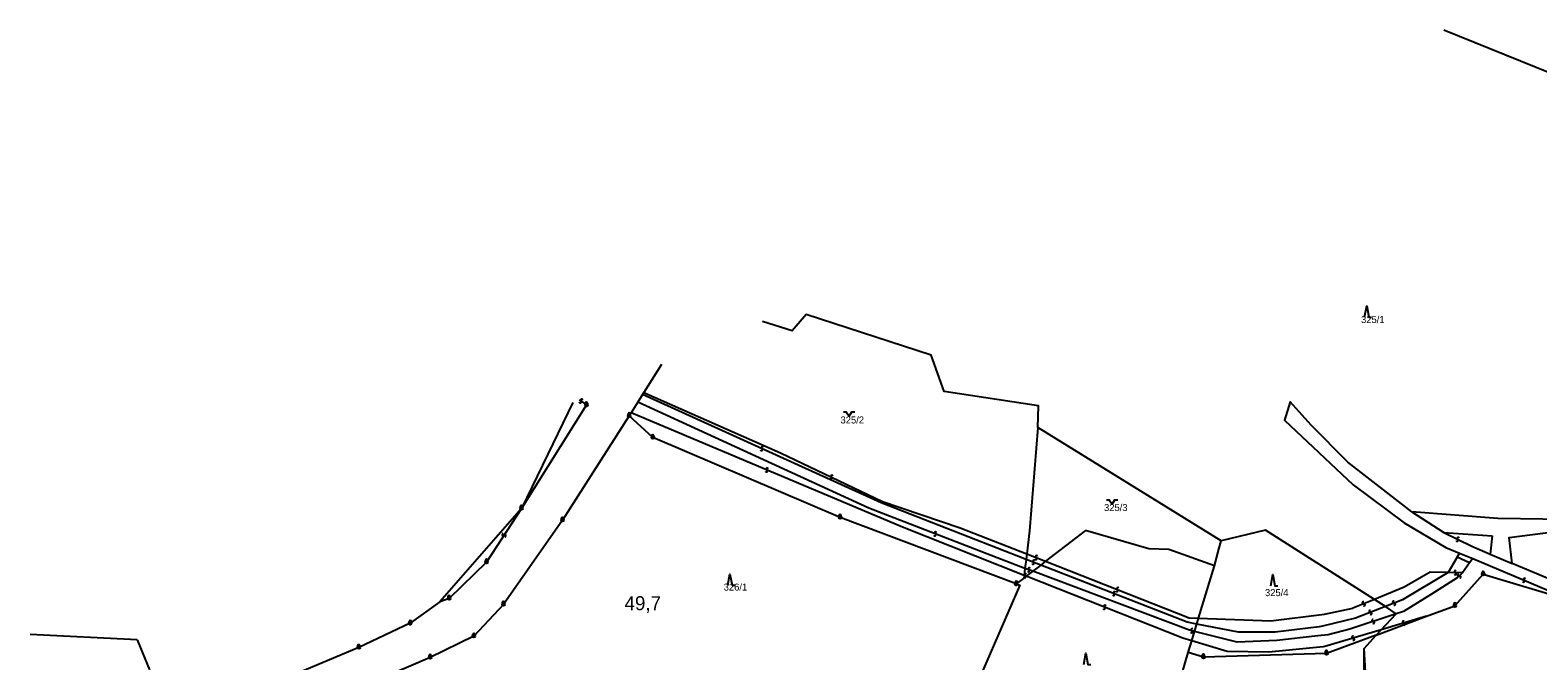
# Model space of a CAD drawing. Extents: x -680102 to -677253, y -1007548 to -1006096.
# Drawn here: x -678248 to -677710, y -1006321 to -1006096 of the extents above; entities that cross this region are included whole.
import ezdxf

# ---------------------------------------------------------------- set-up
doc = ezdxf.new("R2010")
doc.units = 0
for name, color, linetype, lineweight in [('1', 7, 'Continuous', 25), ('11', 7, 'Continuous', 25), ('13', 7, 'Continuous', 25), ('24', 7, 'Continuous', 25), ('25', 7, 'Continuous', 25), ('4', 7, 'Continuous', 25)]:
    doc.layers.add(name, color=color, linetype=linetype, lineweight=lineweight)
doc.layers.add('18', color=7, linetype='Continuous')
doc.layers.add('56', color=7, linetype='Continuous')

msp = doc.modelspace()

# ---------------------------------------------------------------- linework, layer by layer
at = {"layer": '1'}
for p, q in [((-678029.28, -1006226.2), (-678031.01, -1006228.95)), ((-677888.41, -1006237.95), (-677891.42, -1006274.73)), ((-678072.49, -1006266.77), (-678101.56, -1006300)), ((-677893, -1006288.11), (-677893.3, -1006290.62)), ((-677892.62, -1006284.91), (-677893, -1006288.11)), ((-677887.38, -1006286.95), (-677890.24, -1006289.15)), ((-677893.42, -1006291.6), (-677896.13, -1006293.68)), ((-677893.3, -1006290.62), (-677893.42, -1006291.6)), ((-677739.77, -1006301.43), (-677729.71, -1006290.21)), ((-677729.71, -1006290.21), (-677696.92, -1006300.06)), ((-678101.56, -1006300), (-678112.1, -1006307.67)), ((-678112.1, -1006307.67), (-678130.46, -1006316.3)), ((-678209.48, -1006313.6), (-678247.59, -1006311.68)), ((-678209.48, -1006313.6), (-678205.1, -1006324.25)), ((-677772.05, -1006316.61), (-677767.82, -1006311.9)), ((-678130.46, -1006316.3), (-678180.18, -1006337.1)), ((-677770.39, -1006346.95), (-677772.05, -1006316.61))]:
    msp.add_line(p, q, dxfattribs=at)
for points in [[(-677768.42, -1006299.16), (-677807.32, -1006274.53), (-677823.04, -1006278.3), (-677888.41, -1006237.95), (-677888.18, -1006230.26), (-677921.81, -1006225.09), (-677926.47, -1006212.23), (-677971.04, -1006197.75), (-677976.03, -1006203.56), (-677986.61, -1006200.22)], [(-678022.58, -1006215.58), (-678028.83, -1006225.49), (-678029.28, -1006226.2)], [(-678054.11, -1006229.04), (-678063.06, -1006247.41), (-678072.49, -1006266.77)], [(-678031.01, -1006228.95), (-678033.38, -1006232.71), (-678034.06, -1006233.78)], [(-677896.13, -1006293.68), (-677958.9, -1006269.98), (-678025.7, -1006241.54), (-678034.06, -1006233.78), (-678057.89, -1006270.97), (-678078.93, -1006300.97), (-678089.46, -1006312.29), (-678105.02, -1006319.82), (-678141.98, -1006335.73), (-678158.36, -1006345.46), (-678162.46, -1006351.78)], [(-677891.42, -1006274.73), (-677892.39, -1006282.96), (-677892.62, -1006284.91)], [(-677871.38, -1006274.64), (-677885.64, -1006285.61), (-677887.38, -1006286.95)], [(-677825.43, -1006287.18), (-677841.78, -1006281.38), (-677848.81, -1006281.2), (-677871.38, -1006274.64)], [(-677825.43, -1006287.18), (-677823.86, -1006281.33), (-677823.04, -1006278.3)], [(-677834.8, -1006318.04), (-677833.56, -1006313.95), (-677832.54, -1006310.59), (-677831.75, -1006307.98), (-677831.1, -1006305.85), (-677825.43, -1006287.18)], [(-677896.13, -1006293.68), (-677894.83, -1006294.13), (-677918.4, -1006348.18)], [(-677890.24, -1006289.15), (-677892.54, -1006290.92), (-677893.42, -1006291.6)], [(-677767.82, -1006311.9), (-677766.05, -1006310.02), (-677760.67, -1006304.32), (-677764.56, -1006301.73), (-677768.42, -1006299.16)], [(-677767.82, -1006311.9), (-677749.87, -1006305.2), (-677739.77, -1006301.43)], [(-677767.82, -1006311.9), (-677785.59, -1006318.42), (-677829.42, -1006319.73), (-677834.8, -1006318.04)], [(-677845.59, -1006355.04), (-677844.44, -1006351.14), (-677834.8, -1006318.04)]]:
    msp.add_lwpolyline(points, dxfattribs=at)
at = {"layer": '11'}
msp.add_line((-677771.99, -1006347.9), (-677772.05, -1006316.61), dxfattribs=at)
at = {"layer": '13'}
msp.add_lwpolyline([(-677527.75, -1006185.14), (-677585.01, -1006158.46), (-677628.3, -1006138.59), (-677672.94, -1006125.05), (-677743.77, -1006096.49)], dxfattribs=at)
at = {"layer": '24'}
for centre, radius in [((-678049.33, -1006229.94), 0.5), ((-678049.33, -1006229.94), 0.022), ((-678034.06, -1006233.78), 0.5), ((-678034.06, -1006233.78), 0.022), ((-678025.7, -1006241.54), 0.5), ((-678025.7, -1006241.54), 0.022), ((-678072.49, -1006266.77), 0.5), ((-678072.49, -1006266.77), 0.022), ((-678057.89, -1006270.97), 0.5), ((-678057.89, -1006270.97), 0.022), ((-677958.9, -1006269.98), 0.5), ((-677958.9, -1006269.98), 0.022), ((-678084.9, -1006285.86), 0.5), ((-678084.9, -1006285.86), 0.022), ((-677896.13, -1006293.68), 0.5), ((-677896.13, -1006293.68), 0.022), ((-677729.71, -1006290.21), 0.5), ((-677729.71, -1006290.21), 0.022), ((-678098.28, -1006298.81), 0.5), ((-678098.28, -1006298.81), 0.022), ((-678078.93, -1006300.97), 0.5), ((-678078.93, -1006300.97), 0.022), ((-677739.77, -1006301.43), 0.5), ((-677739.77, -1006301.43), 0.022), ((-678112.1, -1006307.67), 0.5), ((-678112.1, -1006307.67), 0.022), ((-678089.46, -1006312.29), 0.5), ((-678089.46, -1006312.29), 0.022), ((-678130.46, -1006316.3), 0.5), ((-678130.46, -1006316.3), 0.022), ((-678105.02, -1006319.82), 0.5), ((-678105.02, -1006319.82), 0.022), ((-677829.42, -1006319.73), 0.5), ((-677829.42, -1006319.73), 0.022), ((-677785.59, -1006318.42), 0.5), ((-677785.59, -1006318.42), 0.022)]:
    msp.add_circle(centre, radius, dxfattribs=at)
for centre in [(-678049.331, -1006229.377), (-678034.061, -1006233.217), (-678025.701, -1006240.977), (-678072.491, -1006266.207), (-678057.891, -1006270.407), (-677958.901, -1006269.417), (-678084.901, -1006285.297), (-677896.131, -1006293.117), (-677729.711, -1006289.647), (-678098.281, -1006298.247), (-678078.931, -1006300.407), (-677739.771, -1006300.867), (-678112.101, -1006307.107), (-678130.461, -1006315.737), (-678089.461, -1006311.727), (-678105.021, -1006319.257), (-677829.421, -1006319.167), (-677785.591, -1006317.857)]:
    msp.add_arc(centre, 0.437, 328.35109, 209.97456, dxfattribs=at)
at = {"layer": '25'}
for points in [[(-677771.96, -1006198.7), (-677771.21, -1006194.7), (-677770.46, -1006198.7), (-677769.46, -1006198.7)], [(-677957.68, -1006232.41), (-677956.68, -1006232.41), (-677955.68, -1006233.91), (-677954.68, -1006232.41), (-677953.68, -1006232.41)], [(-677863.95, -1006263.73), (-677862.95, -1006263.73), (-677861.95, -1006265.23), (-677860.95, -1006263.73), (-677859.95, -1006263.73)], [(-677998.9, -1006294.14), (-677998.15, -1006290.14), (-677997.4, -1006294.14), (-677996.4, -1006294.14)], [(-677805.39, -1006294.36), (-677804.64, -1006290.36), (-677803.89, -1006294.36), (-677802.89, -1006294.36)], [(-677872.05, -1006322.36), (-677871.3, -1006318.36), (-677870.55, -1006322.36), (-677869.55, -1006322.36)]]:
    msp.add_lwpolyline(points, dxfattribs=at)
for centre, radius, start, end in [((-678051.479, -1006228.846), 0.369, 181.55379, 53.50684), ((-678051.042, -1006228.254), 0.368, 0.98133, 233.63071), ((-677986.935, -1006245.823), 0.367, 192.59744, 65.04017), ((-677986.624, -1006245.156), 0.369, 12.83188, 244.79105), ((-677985.155, -1006253.438), 0.367, 194.436, 66.78149), ((-677984.863, -1006252.762), 0.368, 14.45099, 246.3159), ((-677962.152, -1006255.981), 0.369, 191.89018, 63.70463), ((-677961.83, -1006255.319), 0.367, 12.07139, 244.20358), ((-678078.997, -1006276.105), 0.369, 94.0421, 325.88775), ((-678078.383, -1006276.513), 0.368, 274.03414, 146.52698), ((-677925.134, -1006276.202), 0.367, 196.18473, 68.60466), ((-677924.863, -1006275.518), 0.368, 16.41603, 248.37883), ((-677738.947, -1006278.099), 0.368, 191.12821, 63.03716), ((-677738.615, -1006277.442), 0.368, 11.12658, 243.29731), ((-677891.486, -1006288.287), 0.368, 16.71427, 248.86834), ((-677890.136, -1006286.271), 0.368, 195.83202, 68.25709), ((-677889.862, -1006285.588), 0.368, 15.92414, 248.02746), ((-677889.16, -1006284.631), 0.369, 195.92557, 67.86898), ((-677888.883, -1006283.949), 0.367, 15.50175, 248.11371), ((-677893.057, -1006291.111), 0.367, 195.47808, 68.11228), ((-677892.78, -1006290.429), 0.369, 15.92414, 247.88968), ((-677891.752, -1006288.973), 0.367, 196.5212, 68.95184), ((-677739.615, -1006289.282), 0.368, 35.9361, 267.80057), ((-677739.643, -1006290.017), 0.368, 215.62307, 87.972), ((-677738.447, -1006290.588), 0.369, 77.96007, 309.97962), ((-677737.973, -1006291.151), 0.368, 257.61382, 130.14587), ((-677715.308, -1006292.658), 0.368, 194.15102, 66.32397), ((-677715.014, -1006291.983), 0.368, 14.27941, 246.57804), ((-677861.407, -1006297.471), 0.368, 195.69215, 68.11228), ((-677861.131, -1006296.789), 0.368, 15.92414, 248.03333), ((-677860.19, -1006296.011), 0.369, 195.92557, 67.86898), ((-677859.913, -1006295.329), 0.367, 15.50175, 248.11371), ((-677864.757, -1006302.301), 0.367, 195.47808, 68.11228), ((-677864.48, -1006301.619), 0.369, 15.92414, 247.88968), ((-677772.425, -1006300.397), 0.369, 59.5428, 291.22961), ((-677772.154, -1006301.081), 0.368, 239.41155, 111.74434), ((-677770.011, -1006303.475), 0.369, 58.76997, 290.51612), ((-677769.748, -1006304.163), 0.367, 238.652, 111.04959), ((-677761.611, -1006300.175), 0.369, 58.76997, 290.51612), ((-677761.348, -1006300.863), 0.367, 238.652, 111.04959), ((-677833.525, -1006309.954), 0.369, 23.15797, 255.03287), ((-677769.061, -1006306.689), 0.368, 55.49192, 287.31617), ((-677768.838, -1006307.39), 0.368, 235.11357, 107.74553), ((-677758.06, -1006307.255), 0.368, 53.84708, 285.73428), ((-677757.859, -1006307.963), 0.368, 233.60571, 105.96767), ((-677833.713, -1006310.666), 0.367, 203.05884, 75.36007), ((-677776.16, -1006312.655), 0.368, 53.84708, 285.73428), ((-677775.959, -1006313.363), 0.368, 233.60571, 105.96767)]:
    msp.add_arc(centre, radius, start, end, dxfattribs=at)
at = {"layer": '4'}
for p, q in [((-677944.28, -1006264.77), (-678029.28, -1006226.2)), ((-678028.83, -1006225.49), (-677980.14, -1006246.99)), ((-677936.64, -1006273.48), (-678033.38, -1006232.71)), ((-677893.3, -1006290.62), (-677936.64, -1006273.48)), ((-677743.77, -1006275.31), (-677726.44, -1006276.57)), ((-677726.44, -1006276.57), (-677727.14, -1006283.06)), ((-677738.98, -1006284.17), (-677738.07, -1006282.69)), ((-677835.16, -1006307.31), (-677887.38, -1006286.95)), ((-677885.64, -1006285.61), (-677834.46, -1006305.72)), ((-677738.98, -1006284.17), (-677742.15, -1006289.58)), ((-677734.54, -1006286.18), (-677738.98, -1006284.17)), ((-677733.39, -1006284.58), (-677696.92, -1006300.06)), ((-677742.15, -1006289.58), (-677758.41, -1006299.31)), ((-677748.58, -1006289.42), (-677757.86, -1006294.85)), ((-677737.1, -1006289.71), (-677737.48, -1006290.24)), ((-677805.34, -1006306.84), (-677786.23, -1006304.47)), ((-677786.23, -1006304.47), (-677776.16, -1006302.31)), ((-677775.2, -1006305.91), (-677786.92, -1006308.74)), ((-677777.23, -1006309.76), (-677784.93, -1006311.74)), ((-677803.29, -1006313.8), (-677817.37, -1006314.41)), ((-677803.8, -1006310.86), (-677816.85, -1006310.88)), ((-677806.11, -1006317.95), (-677820.96, -1006317.78))]:
    msp.add_line(p, q, dxfattribs=at)
for points in [[(-677694.97, -1006296.56), (-677719.3, -1006286.4), (-677720.42, -1006277.08), (-677703.77, -1006275), (-677691.48, -1006272.31), (-677662.94, -1006266.54), (-677657.67, -1006270.6), (-677644.27, -1006262.08), (-677637.04, -1006261.52), (-677635.64, -1006257.17), (-677620.16, -1006244.01), (-677622.25, -1006241.57), (-677621.08, -1006234.8), (-677611.17, -1006222.35), (-677645.8, -1006186.87), (-677658.37, -1006202.13), (-677672.27, -1006200.39), (-677697.23, -1006229.81), (-677686.75, -1006242), (-677688.84, -1006258.97), (-677693.69, -1006268.44), (-677691.48, -1006272.31)], [(-678051.89, -1006228.1), (-678049.33, -1006229.94), (-678072.49, -1006266.77), (-678084.9, -1006285.86), (-678098.28, -1006298.81), (-678101.56, -1006300)], [(-677901.37, -1006284.97), (-677948.63, -1006266.74), (-678031.01, -1006228.95)], [(-677755.14, -1006267.99), (-677777.92, -1006250.33), (-677791.02, -1006237.09), (-677798.48, -1006228.78), (-677800.51, -1006235.32), (-677776.01, -1006258.33), (-677757.83, -1006271.89), (-677742.97, -1006280.71)], [(-677980.14, -1006246.99), (-677943.84, -1006264.3), (-677916.13, -1006273.63)], [(-677887.38, -1006286.95), (-677892.62, -1006284.91), (-677944.28, -1006264.77)], [(-677693.69, -1006268.44), (-677700.34, -1006270.73), (-677724.43, -1006270.32), (-677755.14, -1006267.99), (-677743.77, -1006275.31), (-677733.79, -1006280.23)], [(-677916.13, -1006273.63), (-677892.39, -1006282.96), (-677885.64, -1006285.61)], [(-677742.97, -1006280.71), (-677738.07, -1006282.69), (-677733.39, -1006284.58)], [(-677733.79, -1006280.23), (-677727.14, -1006283.06), (-677719.3, -1006286.4)], [(-677890.24, -1006289.15), (-677893, -1006288.11), (-677901.37, -1006284.97)], [(-677733.39, -1006284.58), (-677734.54, -1006286.18), (-677737.1, -1006289.71)], [(-677836.7, -1006313), (-677892.54, -1006290.92), (-677893.3, -1006290.62)], [(-677817.37, -1006314.41), (-677832.54, -1006310.59), (-677834.7, -1006310.04), (-677890.24, -1006289.15)], [(-677737.48, -1006290.24), (-677738.95, -1006291.5), (-677748.13, -1006297.34), (-677758.12, -1006303.48)], [(-677737.1, -1006289.71), (-677742.15, -1006289.58), (-677748.58, -1006289.42)], [(-677757.86, -1006294.85), (-677768.42, -1006299.16), (-677776.16, -1006302.31)], [(-677758.41, -1006299.31), (-677764.56, -1006301.73), (-677775.2, -1006305.91)], [(-677758.12, -1006303.48), (-677760.67, -1006304.32), (-677777.23, -1006309.76)], [(-677816.85, -1006310.88), (-677831.75, -1006307.98), (-677835.16, -1006307.31)], [(-677834.46, -1006305.72), (-677831.1, -1006305.85), (-677805.34, -1006306.84)], [(-677786.92, -1006308.74), (-677788.2, -1006308.9), (-677803.8, -1006310.86)], [(-677749.87, -1006305.2), (-677766.05, -1006310.02), (-677786.08, -1006315.99)], [(-677820.96, -1006317.78), (-677833.56, -1006313.95), (-677836.7, -1006313)], [(-677784.93, -1006311.74), (-677788.59, -1006312.15), (-677803.29, -1006313.8)], [(-677786.08, -1006315.99), (-677786.72, -1006316.05), (-677806.11, -1006317.95)]]:
    msp.add_lwpolyline(points, dxfattribs=at)

# ---------------------------------------------------------------- texts
at = {"layer": '18'}
for s, p in [('325/1', (-677773.21, -1006200.78)), ('325/2', (-677958.75, -1006236.53)), ('325/3', (-677864.82, -1006267.72)), ('326/1', (-678000.38, -1006296.03)), ('325/4', (-677807.45, -1006298.01))]:
    msp.add_text(s, height=2.5, dxfattribs=at).set_placement(p)
at = {"layer": '56'}
msp.add_text('49,7', height=5, dxfattribs=at).set_placement((-678035.73, -1006303.03))

doc.saveas('drawing.dxf')
